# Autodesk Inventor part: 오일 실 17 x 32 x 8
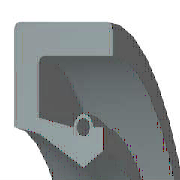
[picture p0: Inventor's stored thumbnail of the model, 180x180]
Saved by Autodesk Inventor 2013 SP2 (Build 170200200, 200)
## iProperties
IsCustomPart: 1
Created: 2012-02
Part Number: 오일 실 17 x 32 x 8
Material: 고무
Description: 오일-실
Document SubType Name: Modeling
Standard: KS B 2804
Designer: test
Standards Organization: KS
Language: ko-KR
Size Designation: S - 17 32 8
Categories: <MemberInstance><Categories><Category DisplayName="샤프트 부품" InternalName="7f7aeb1f-a693-4053-b835-cee3144e0d98" Mnemonic="SHFT"><Category DisplayName="실링" Intern
Density: 0.93 g/cm^3
Author: test
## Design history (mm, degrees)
revolve "본체" stored, may be unused: angle "d17" = 90 deg
revolve "스프링1" stored, may be unused: angle "d18" = 90 deg
body "Solid1"
sketch "스케치1"
  geometry: L1 (0, 16)-(8, 16); L2 (8, 16)-(8, 14.75); L3 (8, 14.75)-(1.75, 14.75); L4 (0, 16)-(0, 10.6); L5 (0, 10.6)-(1.75, 10.25); L6 (1.75, 10.25)-(4.9, 8.5); L7 (4.9, 8.5)-(0, 8.5); L8 (6.3, 9.375)-(6.3, 10.6); L9 (0, 0)-(9.586, 0) reference; L10 (4.9, 8.5)-(6.3, 9.375); L11 (0, 18)-(0, -3) reference; L12 (-1.917, 0)-(11.503, 0) reference; L13 (4.2, 10.6)-(1.75, 11.09); L14 (1.75, 11.09)-(1.75, 14.75); L15 (6.3, 10.6)-(5.6, 10.6); C1 r 0.455 at (4.9, 10.6); A1 r 0.7 centre (4.9, 10.6) between (5.6, 10.6) and (4.2, 10.6)
  constraints: 26 end point, 5 horizontal alignment, 4 perpendicular, 2 centre point, 2 collinear, 2 horizontal, 2 parallel, 2 point on circle, 2 point on line, 2 vertical alignment, 1 coincident
  dimensions: "d0" = 32 diameter of L1 L9 (= SD2); "d1" = 18.75 diameter of L8.start L9 (= ABDM); "d2" = 1.25 distance of L1.end L2.end (computed from SD); "d3" = 0.91 diameter of C1 (= SPDI); "d4" = 1.4 diameter of A1 (= SPDA); "d5" = 17 diameter of L6.end L9 (= NND); "d6" = 20.5 diameter of L5.end L9 (= TKDM); "d7" = 21.2 diameter of L4.end L9 (= HLDM); "d8" = 4.9 distance from line of C1.centre L4 (= SPDST); "d9" = 6.3 distance between parallel lines of L8 L4 (= SDI); "d10" = 8 distance between parallel lines of L2 L4 (= SWDT); "d12" = 1.75 distance between parallel lines of L14 L4 (= SD)
fillet "모깎기1" dims "d11" = 0.3 (= RR)
other parameters: "SD2" = 32 [user parameter; used in 1 equation term], "SWDT" = 8 [user parameter; used in 1 equation term], "RR" = 0.3 [user parameter; used in 1 equation term], "SD" = 1.75 [user parameter; used in 2 equation terms], "NND" = 17 [user parameter; used in 1 equation term], "SPDA" = 1.4 [user parameter; used in 1 equation term], "SPDI" = 0.91 [user parameter; used in 1 equation term], "TKDM" = 20.5 [user parameter; used in 1 equation term], "HLDM" = 21.2 [user parameter; used in 1 equation term], "ABDM" = 18.75 [user parameter; used in 1 equation term], "SDI" = 6.3 [user parameter; used in 1 equation term], "SPDST" = 4.9 [user parameter; used in 1 equation term], "d13" = 0, "d14" = 0, "d15" = 0, "LAB" = 0.35 [user parameter]
